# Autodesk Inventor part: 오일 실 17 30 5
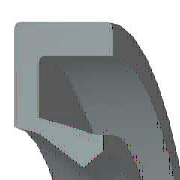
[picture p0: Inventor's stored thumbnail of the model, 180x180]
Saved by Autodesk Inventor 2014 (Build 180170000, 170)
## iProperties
IsCustomPart: 1
Created: 2012-02
Part Number: 오일 실 17 30 5
Material: 고무
Description: 오일 실 - 비스프링, 조립 GA
Document SubType Name: Modeling
Standard: JIS B 2402
Designer: mduedu
Standards Organization: JIS
Language: ko-KR
Size Designation: 17 30 5 A
Categories: <MemberInstance><Categories><Category DisplayName="샤프트 부품" InternalName="7f7aeb1f-a693-4053-b835-cee3144e0d98" Mnemonic="SHFT"><Category DisplayName="실링" Intern
Density: 0.93 g/cm^3
Appearance: Rubber-Black
Author: mduedu
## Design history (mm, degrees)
body "Solid1"
revolve "회전1" stored, may be unused: angle "d27" = 360 deg
fillet "모깎기1" dims "d28" = 0.25 (= 0.05 x b)
sketch "스케치2"
  geometry: L1 (10.636, -3.75)-(11.286, -5); L2 (9.769, -3.438)-(10.636, -3.75); L3 (8.5, -1.375)-(9.769, -3.438); L4 (9.5, -0.75)-(8.5, -1.375); L5 (12.4, -4.375)-(9.5, -0.75); L6 (12.4, -0.25)-(12.4, -4.375); L7 (13.7, -0.25)-(12.4, -0.25); L8 (13.7, 0)-(13.7, -0.25); L9 (15, 0)-(13.7, 0); L10 (15, -5)-(15, 0); L11 (11.286, -5)-(15, -5); L12 (0, -9.6)-(0, 1.6) reference; L13 (28, 0)-(14, 0) reference
  constraints: 22 end point, 3 horizontal, 3 vertical
  dimensions: "d2" = 5 distance of L10.start L9.start (= b); "d4" = 1.3 distance of L9.start L8.start (= 0.1 x dd - 0.1 x Diam); "d6" = 0.25 distance of L8.start L7.start (= 0.05 x b); "d8" = 1 horizontal distance of L4.start L3.start (= 0.0769231 x dd - 0.0769231 x Diam); "d10" = 0.625 vertical distance of L5.start L10.start (= 0.125 x b); "d12" = 1.3 distance of L7.start L6.start (= 0.1 x dd - 0.1 x Diam); "d14" = 0.5 vertical distance of L4.start L6.start (= 0.1 x b); "d16" = 3.71429 distance of L1.end L10.start (= 0.285714 x dd - 0.285714 x Diam); "d18" = 0.65 horizontal distance of L1.start L1.end (= 0.05 x dd - 0.05 x Diam); "d20" = 0.625 vertical distance of L4.start L3.start (= 0.125 x b); "d22" = 1.25 vertical distance of L1.start L1.end (= 0.25 x b); "d24" = 0.86667 horizontal distance of L2.start L1.start (= 0.0666667 x dd - 0.0666667 x Diam); "d26" = 0.3125 vertical distance of L2.start L1.start (= 0.0625 x b); "d29" = 0 distance between parallel lines of L13 L9; "d30" = 8.5 distance from line of L3.start L12 (= 0.5 x Diam); "d31" = 15 distance between parallel lines of L12 L10 (= 0.5 x dd)
other parameters: "Diam" = 17 [user parameter; used in 7 equation terms], "b" = 5 [user parameter; used in 8 equation terms], "d1" = 8 (derived), "d3" = 2 (derived), "d5" = 0.4 (derived), "d7" = 1.53846 (derived), "d9" = 1 (derived), "d11" = 2 (derived), "d13" = 0.8 (derived), "d15" = 5.71429 (derived), "d17" = 1 (derived), "d19" = 1 (derived), "d21" = 2 (derived), "d23" = 1.33333 (derived), "d25" = 0.5 (derived), "d32" = 0
